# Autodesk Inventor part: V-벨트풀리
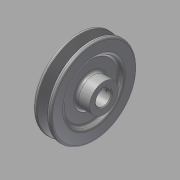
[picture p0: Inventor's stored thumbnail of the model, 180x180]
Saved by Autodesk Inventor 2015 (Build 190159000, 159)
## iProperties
Created: 2015-09
Part Number: V-벨트풀리
Material: 강철, 연강
Document SubType Name: Modeling
Designer: mduedu
Density: 1 g/cm^3
Appearance: 강철
Author: mduedu
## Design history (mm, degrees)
sketch "스케치1"
  geometry: L1 (-10, 0)-(10, 0); L2 (-10, 0)-(-10, 48); L3 (-10, 48)-(-5.976, 48); L4 (-5.976, 48)-(-2.154, 35.5); L5 (-2.154, 35.5)-(2.154, 35.5); L6 (2.154, 35.5)-(5.976, 48); L7 (5.976, 48)-(10, 48); L8 (10, 48)-(10, 0); L9 (0, 0)-(0, 35.5); L10 (-10, 43.5)-(10, 43.5); 3 further points
  constraints: 20 end point, 6 point on line, 3 perpendicular, 2 midpoint, 2 parallel, 2 symmetric about line, 1 coincident, 1 collinear, 1 equal length, 1 horizontal, 1 vertical, 1 vertical alignment
  dimensions: "d0" = 20 distance between parallel lines of L8 L2; "d2" = 96 diameter of L3 L1; "d3" = 87 diameter of L10 L1; "d4" = 4.5 distance between parallel lines of L10 L3 (derived); "d5" = 8 distance between parallel lines of L5 L10; "d6" = 9.2 distance of point (4.6, 43.5) point (-4.6, 43.5); "d7" = 34 deg angle of L6 L4
revolve "회전1" sketch "스케치1" stored, may be unused: angle "d8" = 90 deg
sketch "스케치2"
  geometry: C1 r 16 at (0, 0); 1 further point
  constraints: 1 centre point, 1 coincident
  dimensions: "d9" = 32 diameter of C1
extrude "돌출1" join sketch "스케치2" distance "d10" = 11; taper "d11" = 0 deg
fillet "모깎기1" dims "d12" = 1, "d13" = 0.5, "d14" = 2
sketch "스케치3"
  geometry: C1 r 16 at (0, 0) reference; C2 r 32 at (0, 0); 1 further point
  constraints: 1 centre point, 1 coincident
  dimensions: "d15" = 64 diameter of C2
extrude "돌출2" cut sketch "스케치3" distance "d16" = 4; taper "d17" = 0 deg
fillet "모깎기2" dims "d18" = 3
fillet "모깎기3" dims "d19" = 3
fillet "모깎기4" dims "d20" = 3
sketch "스케치4"
  geometry: C1 r 8.5 at (0, 0); 1 further point
  constraints: 1 centre point, 1 coincident
  dimensions: "d21" = 17 diameter of C1
extrude "돌출3" cut sketch "스케치4" stored distance "d22" = 4; taper "d23" = 0 deg
sketch "스케치5"
  geometry: L1 (-2.5, 8.124)-(2.5, 8.124); L2 (2.5, 8.124)-(2.5, 10.8); L3 (2.5, 10.8)-(-2.5, 10.8); L4 (-2.5, 10.8)-(-2.5, 8.124); A1 r 8.5 centre (0, 0) between (-2.5, 8.124) and (2.5, 8.124) reference; 2 further points
  constraints: 8 end point, 3 point on circle, 2 parallel, 1 horizontal, 1 perpendicular, 1 vertical alignment
  dimensions: "d24" = 5 distance of L2.end L3.end; "d26" = 19.3 distance from line of L3 point (0, -8.5)
extrude "돌출4" cut sketch "스케치5" stored distance "d27" = 4; taper "d28" = 0 deg
chamfer "모따기1" distance "d29" = 1; stored, may be unused: second distance "d30" = 2, angle "d31" = 45 deg
node "작업 평면1"
sketch "스케치6"
  geometry: L1 (-11, 16)-(-11, -16) reference; 2 further points
  constraints: 1 horizontal alignment
  dimensions: "d32" = 5 distance from line of point (-6, 0) L1
hole "구멍1" sketch "스케치6" at (-6, 0) diameter "d33" = 3.242; stored, may be unused: countersink angle "d37" = 90 deg, drill point angle "d39" = 118 deg; dims "d34" = 6, "d35" = 4, "d36" = 2, "d38" = 8
node "솔리드1"
mirror "대칭1"
